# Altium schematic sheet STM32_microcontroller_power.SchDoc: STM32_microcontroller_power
size A4; Date: Not used; ApprovedBy: Not used; CheckedBy: Not used; Author: Not used; CompanyName: STMicroelectronics; DrawnBy: Not used; Engineer: Not used; Organization: Not used; Address1: Not used; Address2: Not used; Address3: Not used; Address4: Not used; DocumentNumber: 4; Revision: Not used; SheetNumber: 4; SheetTotal: 9
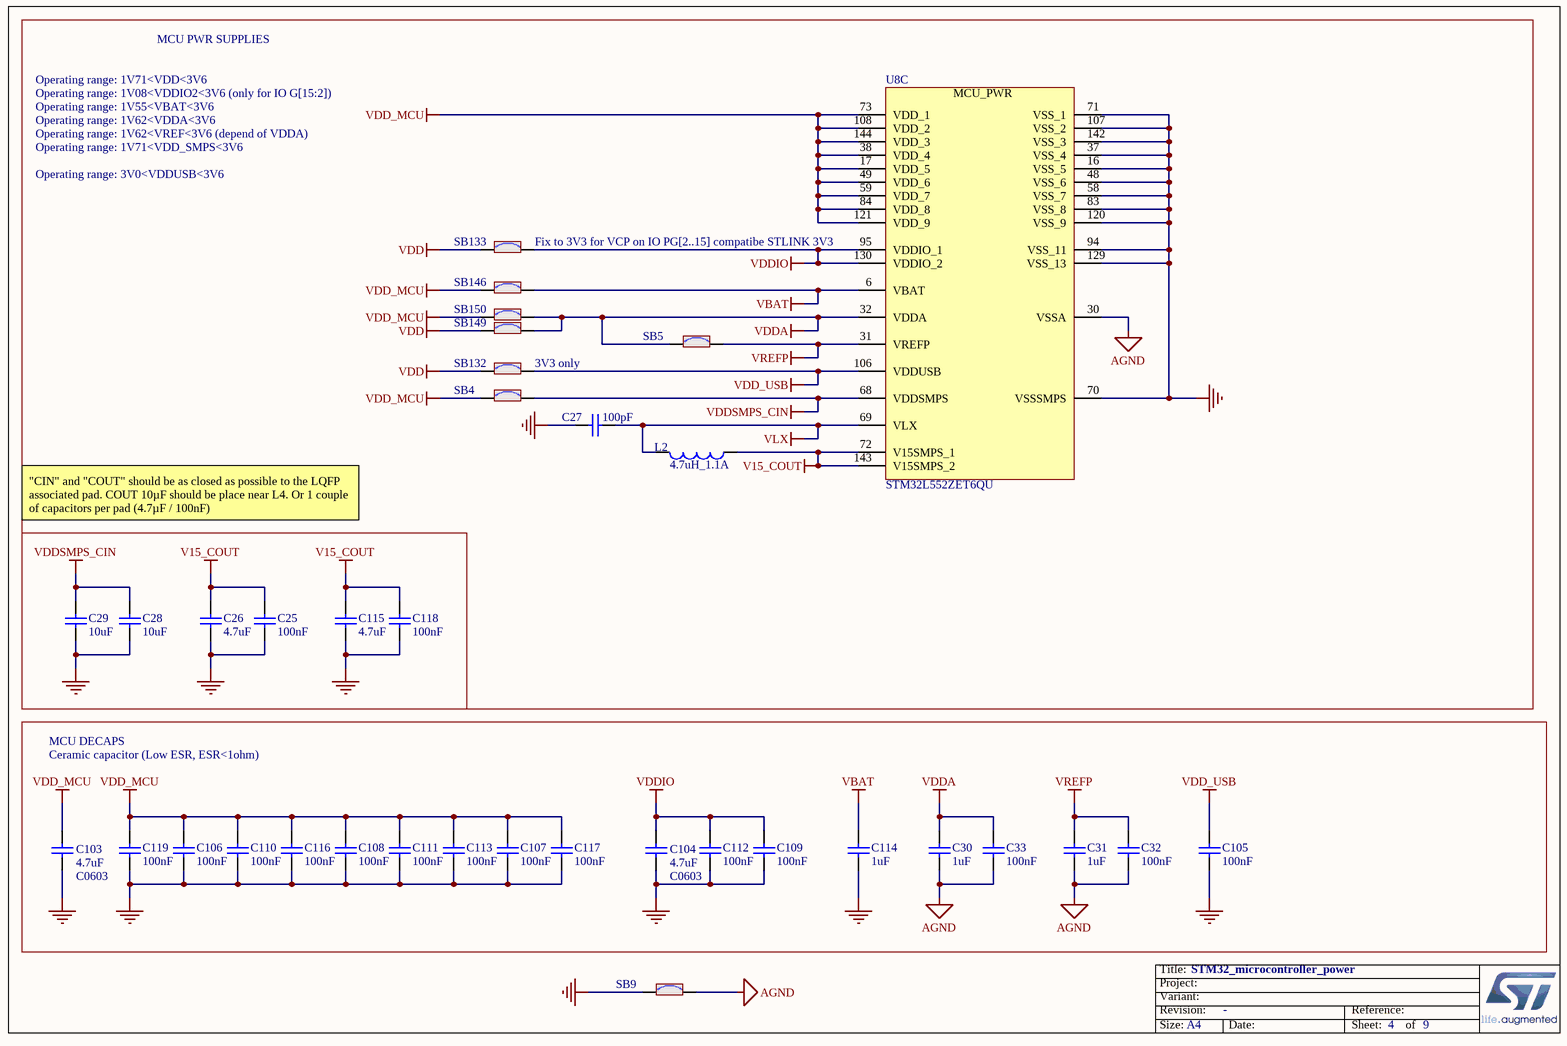
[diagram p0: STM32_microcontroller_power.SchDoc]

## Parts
C25  value 100nF  [C0402]  (hidden comment: Capacitor)
C26  value 4.7uF  [C0402]
C27  value 100pF  [C0402]
C28  value 10uF  [C0402]
C29  value 10uF  [C0402]
C30  value 1uF  [C0603]  (hidden comment: Capacitor)
C31  value 1uF  [C0603]  (hidden comment: Capacitor)
C32  value 100nF  [C0402]  (hidden comment: Capacitor)
C33  value 100nF  [C0402]  (hidden comment: Capacitor)
C103  value 4.7uF  [C0603]
C104  value 4.7uF  [C0603]
C105  value 100nF  [C0402]  (hidden comment: Capacitor)
C106  value 100nF  [C0402]  (hidden comment: Capacitor)
C107  value 100nF  [C0402]  (hidden comment: Capacitor)
C108  value 100nF  [C0402]  (hidden comment: Capacitor)
C109  value 100nF  [C0402]  (hidden comment: Capacitor)
C110  value 100nF  [C0402]  (hidden comment: Capacitor)
C111  value 100nF  [C0402]  (hidden comment: Capacitor)
C112  value 100nF  [C0402]  (hidden comment: Capacitor)
C113  value 100nF  [C0402]  (hidden comment: Capacitor)
C114  value 1uF  [C0603]  (hidden comment: Capacitor)
C115  value 4.7uF  [C0402]
C116  value 100nF  [C0402]  (hidden comment: Capacitor)
C117  value 100nF  [C0402]  (hidden comment: Capacitor)
C118  value 100nF  [C0402]  (hidden comment: Capacitor)
C119  value 100nF  [C0402]  (hidden comment: Capacitor)
L2  value 4.7uH_1.1A  [IND_TDK_MLP2016H4R7MT0S1]  (hidden comment: Inductor)
SB4  (no value)  [SOLDER-BRIDGE_R0603-0R]
SB5  (no value)  [SOLDER-BRIDGE_R0603-0R]
SB9  (no value)  [SOLDER-BRIDGE_R0603-0R]
SB132  (no value)  [SOLDER-BRIDGE_R0603-0R]
SB133  (no value)  [SOLDER-BRIDGE_R0603-0R]
SB146  (no value)  [SOLDER-BRIDGE_R0603-0R]
SB149  (no value)  [SOLDER-BRIDGE_R0603-0R]
SB150  (no value)  [SOLDER-BRIDGE_R0603-0R]
U8  STM32L552ZET6QU  [ICC_LQFP144_20X20_P050]  (part C of 3)

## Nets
AGND: C30.2 C31.2 C32.1 C33.1 SB9.2 U8.30(VSSA)
GND: C25.1 C26.1 C27.1 C28.1 C29.1 C103.1 C104.1 C105.1 C106.1 C107.1 C108.1 C109.1 C110.1 C111.1 C112.1 C113.1 C114.1 C115.1 C116.1 C117.1 C118.1 C119.1 SB9.1 U8.16(VSS_5) U8.37(VSS_4) U8.48(VSS_6) U8.58(VSS_7) U8.70(VSSSMPS) U8.71(VSS_1) U8.83(VSS_8) U8.94(VSS_11) U8.107(VSS_2) U8.120(VSS_9) U8.129(VSS_13) U8.142(VSS_3)
V15_COUT: C25.2 C26.2 C115.2 C118.2 L2.1 U8.72(V15SMPS_1) U8.143(V15SMPS_2)
VBAT: C114.2 SB146.2 U8.6(VBAT)
VDD: SB132.1 SB133.1 SB149.1
VDD_MCU: C103.2 C106.2 C107.2 C108.2 C110.2 C111.2 C113.2 C116.2 C117.2 C119.2 SB4.1 SB146.1 SB150.1 U8.17(VDD_5) U8.38(VDD_4) U8.49(VDD_6) U8.59(VDD_7) U8.73(VDD_1) U8.84(VDD_8) U8.108(VDD_2) U8.121(VDD_9) U8.144(VDD_3)
VDD_USB: C105.2 SB132.2 U8.106(VDDUSB)
VDDA: C30.1 C33.2 SB5.1 SB149.2 SB150.2 U8.32(VDDA)
VDDIO: C104.2 C109.2 C112.2 SB133.2 U8.95(VDDIO_1) U8.130(VDDIO_2)
VDDSMPS_CIN: C28.2 C29.2 SB4.2 U8.68(VDDSMPS)
VLX: C27.2 L2.2 U8.69(VLX)
VREFP: C31.1 C32.2 SB5.2 U8.31(VREFP)

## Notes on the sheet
- MCU PWR SUPPLIES
- Operating range: 1V71<VDD<3V6
- Operating range: 1V08<VDDIO2<3V6 (only for IO G[15:2])
- Operating range: 1V55<VBAT<3V6
- Operating range: 1V62<VDDA<3V6
- Operating range: 3V0<VDDUSB<3V6
- Operating range: 1V71<VDD_SMPS<3V6
- Operating range: 1V62<VREF<3V6 (depend of VDDA)
- Fix to 3V3 for VCP on IO PG[2..15] compatibe STLINK 3V3
- (near SB132) 3V3 only
- "CIN" and "COUT" should be as closed as possible to the LQFP associated pad. COUT 10µF should be place near L4. Or 1 couple of capacitors per pad (4.7µF / 100nF)
- MCU DECAPS
- Ceramic capacitor (Low ESR, ESR<1ohm)

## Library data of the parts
C25 C32 C33 C105-C113 C116-C119 = MCD-00102: Capacitor, MLCC, 100nF, 16V, X7R, 10%, 0402, T=0,5mm; Manufacturer_Part_Number: CC0402KRX7R7BB104; Manufacturer: YAGEO; Alternate_Manufacturer_Part_Number: GCM155R71C104KA55D; Alternate_Manufacturer: MURATA; Provided_By: SUBCO
C26 C115 = MCD-01356: Capacitor, MLCC, 4.7uF, 6V3, X5R, 20%, 0402, T=0,5mm; Manufacturer_Part_Number: GRM155R60J475ME47; Manufacturer: MURATA; ECCN_US: EAR99; ECCN_EU: NEC; Provided_By: Subcon; Initial_Board_Reference: MB1372
C27 = MCD-00205: Capacitor, MLCC, 100pF, 50V, NPO, 5%, 0402, T=0,5mm; Manufacturer_Part_Number: CC0402JRNPO9BN101; Manufacturer: YAGEO; Provided_By: Subcon; Initial_Board_Reference: MB1361
C28 C29 = MCD-01355: Capacitor, MLCC, 10uF, 4V, X5R, 20%, 0402, T=0,5mm; Manufacturer_Part_Number: GRM155R60G106ME44; Manufacturer: MURATA; ECCN_US: EAR99; ECCN_EU: NEC; Provided_By: Subcon; Initial_Board_Reference: MB1372
C30 C31 C114 = MCD-00010: Capacitor, MLCC, 1uF, 16V, X5R, 10%, 0603, T=0,8mm; Manufacturer_Part_Number: CC0603KRX5R7BB105; Manufacturer: YAGEO; Provided_By: SUBCO
C103 C104 = MCD-01121: Capacitor, MLCC, 4.7µF, 10V, X5R, 20%, 0603, T=0,8mm; Manufacturer_Part_Number: GRM188R61A475ME15; Manufacturer: MURATA; ECCN_US: EAR99; ECCN_EU: NEC; Provided_By: Subcon; Initial_Board_Reference: MB1361
L2 = MCD-01786: Power Inductor 4.7uH 1.1A 160 mOHM 20% SMD Multilayer ferrite.; Manufacturer_Part_Number: MLP2016H4R7MT0S1; Manufacturer: TDK; Provided_By: SUBCO
SB4 SB5 SB9 SB132 SB133 SB146 SB149 SB150 = MCD-00071: Solder Bridge ON; Part_Type: Mechanical; Provided_By: Subcon; Initial_Board_Reference: MB1274
U8 = MCD-01055: STM32L552ZET6Q MCU,LQFP144 20x20, 0.5, no AES, Q for Int SMPS; Part_Type: IC; Manufacturer: STMICROELECTRONICS; BMS_Part_Number: 9175310; ECCN_US: 3A991A2; ECCN_EU: NEC; Provided_By: SUBCO with ST control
